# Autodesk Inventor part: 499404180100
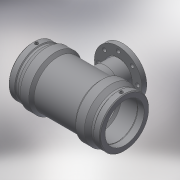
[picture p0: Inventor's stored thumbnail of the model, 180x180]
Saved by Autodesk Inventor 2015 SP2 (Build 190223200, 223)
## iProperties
Created: 2017-06
Part Number: 499404180100
Material: Generic
Description: PLASSON FLANGED TEE 180x100x180
Document SubType Name: Modeling
Designer: KIM
Mass: 57.3761 g
Surface Area: 241.06 cm^2
Volume: 57.3761 cm^3
Density: 1 g/cm^3
Appearance: Default
Author: KIM
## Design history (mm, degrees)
derived "499404.ipt"
feature "Solid1::499404.ipt"
tag "TaggingFeature1"
body "Solid1"
other parameters: "d13" = 422, "d14" = 17.6296, "d17" = 162, "d19" = 3.52592, "d20" = 168 deg, "d22" = 227.85, "d23" = 245, "d24" = 221.0145, "d25" = 135 deg, "d26" = 295.4, "d27" = 135 deg, "d29" = 116, "d35" = 15, "d39" = 5 deg, "d45" = 4, "d46" = 14, "d47" = 0, "d48" = -225, "d55" = 220.5, "d56" = 245, "d57" = 147.7, "d58" = 135 deg, "d59" = 106, "d60" = 106, "d61" = 135 deg, "d62" = 225, "d72" = 192.01, "d73" = 96.005, "d74" = -225, "d84" = 225, "d87" = 158, "d90" = 125, "d91" = 15 deg, "d93" = 22, "d95" = 4.74, "d97" = 18, "d100" = 0, "d102" = 360 deg, "d105" = 0, "d107" = 0, "d108" = 3, "d109" = 0, "d110" = 31.8, "d111" = 10.6, "L_" = 422, "L_1" = 106, "D_" = 245, "A_" = 116, "d_2" = 12, "H_" = 225, "t_" = 22, "d_1" = 158, "s_" = 18
